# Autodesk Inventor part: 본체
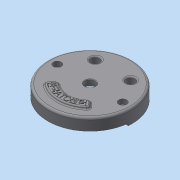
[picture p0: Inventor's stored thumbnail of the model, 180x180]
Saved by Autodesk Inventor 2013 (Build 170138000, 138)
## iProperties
Created: 2015-04
Part Number: 본체
Material: 일반
Document SubType Name: Modeling
Designer: Administrator
Density: 1 g/cm^3
Author: Administrator
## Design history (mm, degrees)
sketch "스케치1"
  geometry: C1 r 95 at (0, 0); 1 further point
  constraints: 1 centre point, 1 coincident
  dimensions: "d0" = 190 diameter of C1
extrude "돌출1" new body sketch "스케치1" distance "d1" = 32; taper "d2" = 0 deg
feature "쉘1" dims "d3" = 14, "d4" = 5
sketch "스케치2"
  geometry: C1 r 90 at (0, 0) reference; C2 r 35 at (0, 0)
  constraints: 1 centre point, 1 coincident
  dimensions: "d5" = 70 diameter of C2
extrude "돌출2" join sketch "스케치2" distance "d6" = 10; taper "d7" = -10 deg
sketch "스케치3"
  geometry: C1 r 35 at (0, 0) reference; A1 r 41 centre (0, -19) between (-40.794, -14.9) and (40.794, -14.9); A2 r 59 centre (0, -19) between (-58.704, -13.1) and (58.704, -13.1); A3 r 9 centre (-49.749, -14) between (-40.794, -14.9) and (-58.704, -13.1); A4 r 9 centre (49.749, -14) between (58.704, -13.1) and (40.794, -14.9)
  constraints: 8 point on circle, 4 centre point, 2 tangent, 1 coincident, 1 vertical alignment
  dimensions: "d8" = 82 diameter of A1; "d9" = 19 distance of A1.centre C1.centre; "d10" = 118 diameter of A2; "d11" = 18 diameter of A3; "d12" = 18 diameter of A4; "d13" = 14 vertical distance of C1.centre A3.centre; "d14" = 14 vertical distance of C1.centre A4.centre
extrude "돌출3" cut sketch "스케치3" distance "d15" = 7; taper "d16" = 0 deg
sketch "스케치4"
  geometry: L1 (-89.196, 12)-(-40.249, 12); L2 (40.249, 12)-(89.196, 12); C1 r 35 at (0, 0) reference; A1 r 90 centre (0, 0) between (89.196, 12) and (-89.196, 12) reference; A2 r 42 centre (0, 0) between (40.249, 12) and (-40.249, 12)
  constraints: 4 end point, 4 point on circle, 2 horizontal, 1 centre point, 1 coincident
  dimensions: "d17" = 84 diameter of A2; "d19" = 12 distance from line of C1.centre L1; "d20" = 12 distance from line of C1.centre L2
extrude "돌출4" cut sketch "스케치4" distance "d21" = 7; taper "d22" = 0 deg
fillet "모깎기1" dims "d23" = 10
sketch "스케치5"
  geometry: C1 r 95 at (0, 0) reference; C2 r 15 at (-40, 52); C3 r 9 at (-74, 0)
  constraints: 2 centre point, 1 horizontal alignment
  dimensions: "d24" = 30 diameter of C2; "d25" = 18 diameter of C3; "d26" = 52 vertical distance of C1.centre C2.centre; "d27" = 40 horizontal distance of C1.centre C2.centre; "d28" = 74 distance of C1.centre C3.centre
extrude "돌출5" join sketch "스케치5" distance "d29" = 32; taper "d30" = 0 deg
sketch "스케치6"
  geometry: C1 r 15 at (0, 0) reference; C2 r 10 at (0, 0); 1 further point
  constraints: 1 centre point, 1 coincident
  dimensions: "d31" = 20 diameter of C2
extrude "돌출6" cut sketch "스케치6" stored distance "d32" = 32; taper "d33" = 0 deg
sketch "스케치7"
  geometry: C1 r 9 at (-74, 0) reference
hole "구멍1" sketch "스케치7" at (-74, 0) diameter "d34" = 11; stored, may be unused: countersink angle "d38" = 90 deg, drill point angle "d40" = 118 deg; dims "d35" = 6, "d36" = 18, "d37" = 11, "d39" = 8
sketch "스케치8"
  geometry: L1 (-20, 6)-(20, 6); L2 (20, 6)-(20, -6); L3 (20, -6)-(-20, -6); L4 (-20, -6)-(-20, 6); L5 (-86, 20)-(-74, 20); L6 (-74, 20)-(-74, -20); L7 (-74, -20)-(-86, -20); L8 (-86, -20)-(-86, 20); C1 r 10 at (0, 0) reference; C2 r 10 at (-80, 0) reference; C3 r 15 at (-80, 0) reference; 5 further points
  constraints: 16 end point, 4 midpoint, 4 parallel, 2 horizontal, 2 horizontal alignment, 2 perpendicular, 2 vertical alignment
  dimensions: "d41" = 12 distance of L3.end L1.start; "d43" = 12 distance of L5.start L5.end; "d44" = 40 distance of L1.start L1.end; "d45" = 40 distance of L5.end L6.end
extrude "돌출7" cut sketch "스케치8" distance "d46" = 3; taper "d47" = 0 deg
sketch "스케치9"
  geometry: C1 r 33.237 at (0, 0) reference
hole "구멍2" sketch "스케치9" at (0, 0) diameter "d48" = 23; stored, may be unused: countersink angle "d52" = 90 deg, drill point angle "d54" = 118 deg; dims "d49" = 6, "d50" = 50, "d51" = 15, "d53" = 8
chamfer "모따기1" distance "d55" = 1; stored, may be unused: second distance "d56" = 2, angle "d57" = 45 deg
fillet "모깎기2" dims "d58" = 3
node "작업 평면1"
sketch "스케치10"
  geometry: L1 (-89.658, -7.844)-(-101.855, -8.911); L2 (89.658, -7.844)-(101.855, -8.911); L3 (-74, 0)-(74, 0); C1 r 95 at (0, 0) reference; C2 r 10 at (40, 52) reference; C3 r 10 at (-40, 52) reference; C4 r 15 at (40, 52) reference; C5 r 15 at (-40, 52) reference; C6 r 5.5 at (74, 0) reference; C7 r 9 at (74, 0) reference; C8 r 5.5 at (-74, 0) reference; C9 r 9 at (-74, 0) reference; A1 r 90 centre (0, 0) between (-89.658, -7.844) and (89.658, -7.844) reference; A2 r 102.244 centre (0, 0) between (-101.855, -8.911) and (101.855, -8.911); A3 r 90 centre (0, 0) between (-89.658, -7.844) and (89.658, -7.844); 1 further point
  constraints: 6 end point, 6 point on circle, 2 centre point, 2 coincident, 1 concentric, 1 horizontal
  dimensions: "d62" = 204.48899 diameter of A2; "d63" = 5 deg angle of L1 L3; "d64" = 5 deg angle of L2 L3; "d65" = 7.84402 vertical distance of L1.start C8.centre; "d66" = 7.84402 vertical distance of L2.start C6.centre
extrude "돌출8" cut sketch "스케치10" distance "d67" = 5; taper "d68" = 0 deg
fillet "모깎기3" dims "d69" = 3
sketch "스케치11"
  geometry: L1 (-72, 0)-(0, 0); L2 (36.062, -36.062)-(50.912, -50.912); L3 (-36.062, -36.062)-(-50.912, -50.912); C1 r 12.5 at (0, 0) reference; C2 r 92 at (0, 0) reference; A1 r 51 centre (0, 0) between (-36.062, -36.062) and (36.062, -36.062); A2 r 72 centre (0, 0) between (-50.912, -50.912) and (50.912, -50.912); A3 r 72 centre (0, 0) between (-50.912, 50.912) and (-52.67, 49.09); 1 further point
  constraints: 6 end point, 6 point on circle, 3 centre point, 2 coincident, 1 horizontal, 1 point on line, 2 other
  dimensions: "d71" = 102 diameter of A1; "d74" = 45 deg angle of L3 L1; "d75" = 90 deg angle of L2 L3; "d77" = 72 radius of A2; "d78" = 36.06245 horizontal distance of L3.start C1.centre; "d79" = 36.06245 horizontal distance of L2.start C1.centre
extrude "돌출9" join sketch "스케치11" distance "d80" = 5; taper "d81" = 0 deg
fillet "모깎기4" dims "d82" = 5
fillet "모깎기5" dims "d83" = 3
sketch "스케치12"
  geometry: C1 r 68 at (0, 0); 1 further point
  constraints: 1 centre point, 1 coincident, 1 other
  dimensions: "d85" = 136 diameter of C1
feature "엠보싱1" sketch "스케치12" dims "d8" = 82, "d9" = 19, "d10" = 118, "d11" = 18, "d12" = 18, "d13" = 14, "d14" = 14, "d86" = 0.5, "d87" = 0
fillet "모깎기7" dims "d88" = 3
fillet "모깎기8" dims "d89" = 0.3
fillet "모깎기9" dims "d90" = 1
fillet "모깎기10" dims "d91" = 5
node "솔리드1"
mirror "대칭1"
node "투영된 루프1"
node "절단 모서리 투영1"
other parameters: "d18" = 12, "d59" = 5, "d70" = 144, "d72" = 90 deg, "d73" = 45 deg
